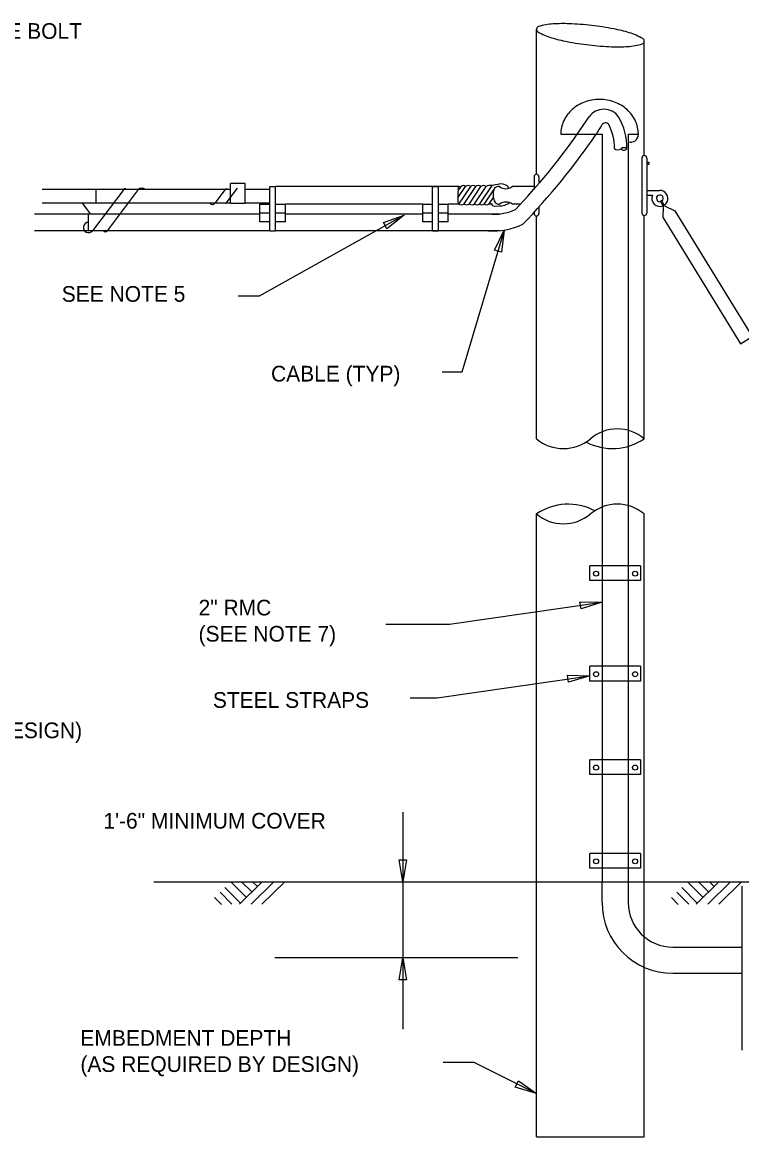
# Model space of a CAD drawing. Extents: x 1299104.8 to 1299141.6, y 239639.8 to 239661.8.
# Drawn here: x 1299124.15 to 1299129.65, y 239645.25 to 239653.76 of the extents above; entities that cross this region are included whole.
import ezdxf

# ---------------------------------------------------------------- set-up
doc = ezdxf.new("R2010")
doc.units = 0
doc.layers.add('DIM TXT', color=7, linetype='Continuous')

msp = doc.modelspace()

# ---------------------------------------------------------------- linework, layer by layer
at = {"layer": 'DIM TXT'}
for p, q in [((1299128.0798, 239652.6017), (1299128.0798, 239653.7122)), ((1299128.9048, 239652.7446), (1299128.9048, 239653.6171)), ((1299128.3917, 239652.9076), (1299128.4821, 239653.0418)), ((1299128.2653, 239652.9076), (1299128.5815, 239652.9076)), ((1299128.5815, 239652.9076), (1299128.5815, 239650.6817)), ((1299128.7815, 239652.9076), (1299128.7815, 239650.6929)), ((1299128.7815, 239652.9076), (1299128.8594, 239652.9076)), ((1299128.886, 239652.7258), (1299128.886, 239652.3058)), ((1299128.9235, 239652.7258), (1299128.9235, 239652.3058)), ((1299128.9235, 239652.6952), (1299128.9385, 239652.6952)), ((1299128.9235, 239652.6802), (1299128.9385, 239652.6802)), ((1299128.9385, 239652.6952), (1299128.9385, 239652.6802)), ((1299128.061, 239652.583), (1299128.061, 239652.4875)), ((1299128.0985, 239652.583), (1299128.0985, 239652.5305)), ((1299125.7398, 239652.4857), (1299124.2985, 239652.4857)), ((1299124.9225, 239652.4857), (1299124.6837, 239652.1707)), ((1299124.711, 239652.3807), (1299124.711, 239652.4857)), ((1299125.034, 239652.4857), (1299124.7953, 239652.1707)), ((1299125.6983, 239652.4857), (1299125.6187, 239652.3807)), ((1299125.7915, 239652.4963), (1299125.7039, 239652.3807)), ((1299125.7398, 239652.3807), (1299125.7398, 239652.5307)), ((1299125.8523, 239652.5307), (1299125.7398, 239652.5307)), ((1299125.8523, 239652.3807), (1299125.8523, 239652.5307)), ((1299126.0398, 239652.4857), (1299125.8523, 239652.4857)), ((1299126.0398, 239652.1707), (1299126.0398, 239652.5082)), ((1299126.0398, 239652.5082), (1299126.0848, 239652.5082)), ((1299126.0848, 239652.1707), (1299126.0848, 239652.5082)), ((1299127.485, 239652.5082), (1299126.0848, 239652.5082)), ((1299127.2848, 239652.1707), (1299127.2848, 239652.5082)), ((1299127.2848, 239652.5082), (1299127.3298, 239652.5082)), ((1299127.3298, 239652.1707), (1299127.3298, 239652.5082)), ((1299127.4789, 239652.4213), (1299127.5369, 239652.5082)), ((1299127.4821, 239652.5082), (1299127.4792, 239652.4291)), ((1299127.4809, 239652.4745), (1299127.5043, 239652.5096)), ((1299127.4821, 239652.5082), (1299127.505, 239652.5106)), ((1299127.4868, 239652.3732), (1299127.5769, 239652.5082)), ((1299127.5268, 239652.3755), (1299127.6153, 239652.5082)), ((1299127.5666, 239652.3755), (1299127.6551, 239652.5082)), ((1299127.6065, 239652.3755), (1299127.695, 239652.5082)), ((1299127.6464, 239652.3755), (1299127.7404, 239652.5164)), ((1299127.6818, 239652.3755), (1299127.7529, 239652.4821)), ((1299127.7536, 239652.5176), (1299127.7369, 239652.5161)), ((1299127.7663, 239652.5212), (1299127.7536, 239652.5176)), ((1299127.785, 239652.5237), (1299127.7663, 239652.5212)), ((1299127.8048, 239652.5283), (1299127.785, 239652.5237)), ((1299127.824, 239652.5252), (1299127.8048, 239652.5283)), ((1299127.8402, 239652.5212), (1299127.824, 239652.5252)), ((1299127.861, 239652.5121), (1299127.8402, 239652.5212)), ((1299127.8691, 239652.4943), (1299127.861, 239652.5121)), ((1299128.061, 239652.5082), (1299127.8949, 239652.5082)), ((1299128.9235, 239652.4787), (1299129.0236, 239652.4787)), ((1299125.7398, 239652.3807), (1299124.2985, 239652.3807)), ((1299124.6702, 239652.2982), (1299124.6077, 239652.3807)), ((1299125.7398, 239652.3807), (1299125.8523, 239652.3807)), ((1299126.0398, 239652.3807), (1299125.8523, 239652.3807)), ((1299127.4792, 239652.4291), (1299127.4778, 239652.3981)), ((1299127.4778, 239652.3981), (1299127.4792, 239652.3892)), ((1299127.4792, 239652.3892), (1299127.4868, 239652.3732)), ((1299127.7173, 239652.3755), (1299127.75, 239652.4245)), ((1299127.864, 239652.3758), (1299127.8463, 239652.3678)), ((1299127.8706, 239652.3865), (1299127.864, 239652.3758)), ((1299128.9235, 239652.4412), (1299128.9672, 239652.4412)), ((1299129.0377, 239652.4011), (1299129.0293, 239652.3966)), ((1299129.0517, 239652.3548), (1299129.0293, 239652.3966)), ((1299129.059, 239652.3614), (1299129.0377, 239652.4011)), ((1299125.9648, 239652.2982), (1299124.2398, 239652.2982)), ((1299124.6523, 239652.1707), (1299124.6523, 239652.2982)), ((1299125.9648, 239652.2382), (1299125.9648, 239652.3732)), ((1299125.9648, 239652.3732), (1299126.0398, 239652.3732)), ((1299126.0398, 239652.3057), (1299125.9648, 239652.3057)), ((1299126.0848, 239652.3732), (1299126.1598, 239652.3732)), ((1299126.1598, 239652.3057), (1299126.0848, 239652.3057)), ((1299126.1598, 239652.2382), (1299126.1598, 239652.3732)), ((1299127.2098, 239652.3732), (1299126.1598, 239652.3732)), ((1299127.2098, 239652.2982), (1299126.1598, 239652.2982)), ((1299127.2098, 239652.2382), (1299127.2098, 239652.3732)), ((1299127.2098, 239652.3732), (1299127.2848, 239652.3732)), ((1299127.2848, 239652.3057), (1299127.2098, 239652.3057)), ((1299127.3298, 239652.3732), (1299127.4048, 239652.3732)), ((1299127.4048, 239652.3057), (1299127.3298, 239652.3057)), ((1299127.4048, 239652.2382), (1299127.4048, 239652.3732)), ((1299127.4868, 239652.3732), (1299127.4048, 239652.3732)), ((1299127.8004, 239652.2982), (1299127.4048, 239652.2982)), ((1299127.7283, 239652.3739), (1299127.7187, 239652.3728)), ((1299127.7339, 239652.3739), (1299127.7283, 239652.3739)), ((1299127.743, 239652.3743), (1299127.7339, 239652.3739)), ((1299127.7386, 239652.3673), (1299127.7339, 239652.3739)), ((1299127.7462, 239652.3618), (1299127.7386, 239652.3673)), ((1299127.7582, 239652.3553), (1299127.7462, 239652.3618)), ((1299127.7967, 239652.3586), (1299127.7582, 239652.3553)), ((1299127.8139, 239652.3582), (1299127.7967, 239652.3586)), ((1299127.8245, 239652.3612), (1299127.8139, 239652.3582)), ((1299127.8356, 239652.3627), (1299127.8245, 239652.3612)), ((1299127.8463, 239652.3678), (1299127.8356, 239652.3627)), ((1299127.9566, 239652.3732), (1299127.8964, 239652.3732)), ((1299128.061, 239652.3112), (1299128.061, 239652.3024)), ((1299128.0985, 239652.3522), (1299128.0985, 239652.3024)), ((1299129.0495, 239652.2684), (1299129.0517, 239652.3548)), ((1299129.059, 239652.3614), (1299129.139, 239652.3235)), ((1299129.139, 239652.3235), (1299129.731, 239651.3613)), ((1299127.069, 239652.2891), (1299125.9581, 239651.6699)), ((1299126.0398, 239652.2382), (1299125.9648, 239652.2382)), ((1299126.1598, 239652.2382), (1299126.0848, 239652.2382)), ((1299127.2848, 239652.2382), (1299127.2098, 239652.2382)), ((1299127.4048, 239652.2382), (1299127.3298, 239652.2382)), ((1299128.0798, 239650.5805), (1299128.0798, 239652.2836)), ((1299128.5815, 239652.2506), (1299128.5815, 239647.1944)), ((1299128.7815, 239652.2618), (1299128.7815, 239647.1944)), ((1299128.9048, 239650.5805), (1299128.9048, 239652.2871)), ((1299129.0495, 239652.2684), (1299129.6416, 239651.3063)), ((1299126.0398, 239652.1707), (1299124.2398, 239652.1707)), ((1299126.0398, 239652.1707), (1299126.0848, 239652.1707)), ((1299127.8004, 239652.1707), (1299126.0848, 239652.1707)), ((1299127.2848, 239652.1707), (1299127.3298, 239652.1707)), ((1299127.8333, 239652.1748), (1299127.5087, 239651.0887)), ((1299125.9581, 239651.6699), (1299125.7968, 239651.6699)), ((1299129.6416, 239651.3063), (1299129.731, 239651.3613)), ((1299127.5087, 239651.0887), (1299127.3587, 239651.0887)), ((1299128.0798, 239647.1944), (1299128.0798, 239650.0052)), ((1299128.9048, 239647.1944), (1299128.9048, 239650.0052)), ((1299128.8755, 239649.6094), (1299128.4875, 239649.6094)), ((1299128.4875, 239649.4969), (1299128.4875, 239649.6094)), ((1299128.8755, 239649.6094), (1299128.8755, 239649.4969)), ((1299128.8755, 239649.4969), (1299128.4875, 239649.4969)), ((1299127.4155, 239649.1637), (1299128.5815, 239649.3313)), ((1299126.9279, 239649.1637), (1299127.4155, 239649.1637)), ((1299128.8755, 239648.8409), (1299128.4875, 239648.8409)), ((1299128.4875, 239648.7284), (1299128.4875, 239648.8409)), ((1299128.8755, 239648.8409), (1299128.8755, 239648.7284)), ((1299127.3215, 239648.5999), (1299128.4875, 239648.7675)), ((1299128.8755, 239648.7284), (1299128.4875, 239648.7284)), ((1299127.1126, 239648.5999), (1299127.3215, 239648.5999)), ((1299128.4875, 239648.0143), (1299128.4875, 239648.1268)), ((1299128.8755, 239648.1268), (1299128.4875, 239648.1268)), ((1299128.8755, 239648.1268), (1299128.8755, 239648.0143)), ((1299128.8755, 239648.0143), (1299128.4875, 239648.0143)), ((1299127.0573, 239647.7268), (1299127.0573, 239646.0673)), ((1299128.8755, 239647.4105), (1299128.4875, 239647.4105)), ((1299128.4875, 239647.298), (1299128.4875, 239647.4105)), ((1299128.8755, 239647.4105), (1299128.8755, 239647.298)), ((1299128.8755, 239647.298), (1299128.4875, 239647.298)), ((1299125.1536, 239647.1944), (1299131.9317, 239647.1944)), ((1299125.7411, 239647.1944), (1299125.8608, 239647.0737)), ((1299125.8086, 239647.0228), (1299125.9815, 239647.1944)), ((1299125.8242, 239647.1944), (1299125.9018, 239647.1162)), ((1299125.8968, 239647.0225), (1299126.07, 239647.1944)), ((1299125.9084, 239647.1944), (1299125.9447, 239647.1579)), ((1299125.9803, 239647.0222), (1299126.1538, 239647.1944)), ((1299128.0798, 239645.2453), (1299128.0798, 239647.1944)), ((1299128.5815, 239647.036), (1299128.5815, 239647.1964)), ((1299128.7815, 239647.1944), (1299128.7815, 239647.036)), ((1299128.9048, 239645.2453), (1299128.9048, 239647.1944)), ((1299129.235, 239647.1944), (1299129.3548, 239647.0737)), ((1299129.3026, 239647.0228), (1299129.4754, 239647.1944)), ((1299129.3182, 239647.1944), (1299129.3957, 239647.1162)), ((1299129.3908, 239647.0225), (1299129.564, 239647.1944)), ((1299129.4024, 239647.1944), (1299129.4386, 239647.1579)), ((1299129.4743, 239647.0222), (1299129.6478, 239647.1944)), ((1299125.6595, 239647.1144), (1299125.7501, 239647.023)), ((1299125.6968, 239647.1514), (1299125.8161, 239647.0312)), ((1299129.1535, 239647.1144), (1299129.2441, 239647.023)), ((1299129.1908, 239647.1514), (1299129.3101, 239647.0312)), ((1299129.6499, 239647.1607), (1299129.65, 239646.2247)), ((1299125.6177, 239647.0727), (1299125.6694, 239647.0206)), ((1299129.1116, 239647.0727), (1299129.1633, 239647.0206)), ((1299129.123, 239646.6944), (1299129.6499, 239646.6944)), ((1299127.9363, 239646.6122), (1299126.0781, 239646.6122)), ((1299129.123, 239646.4944), (1299129.6499, 239646.4944)), ((1299129.65, 239646.247), (1299129.65, 239645.9071)), ((1299129.6495, 239646.2246), (1299129.6483, 239646.2245)), ((1299127.366, 239645.8146), (1299127.5998, 239645.8146)), ((1299127.5998, 239645.8146), (1299128.0798, 239645.5751)), ((1299128.0798, 239645.2453), (1299128.9048, 239645.2453))]:
    msp.add_line(p, q, dxfattribs=at)
for points in [[(1299126.9351, 239652.1859), (1299126.9093, 239652.2338), (1299127.069, 239652.2891)], [(1299127.8116, 239652.0072), (1299127.7595, 239652.0227), (1299127.8333, 239652.1748)], [(1299128.4205, 239649.2797), (1299128.4124, 239649.3335), (1299128.5815, 239649.3313)], [(1299128.3256, 239648.7186), (1299128.3185, 239648.7725), (1299128.4875, 239648.7675)], [(1299127.0301, 239647.3612), (1299127.0845, 239647.3612), (1299127.0573, 239647.1944)], [(1299127.0845, 239646.4454), (1299127.0301, 239646.4454), (1299127.0573, 239646.6122)], [(1299127.9179, 239645.6238), (1299127.9417, 239645.6727), (1299128.0798, 239645.5751)]]:
    msp.add_lwpolyline(points, close=True, dxfattribs=at)
for centre in [(1299128.5357, 239649.5491), (1299128.8339, 239649.5491), (1299128.5357, 239648.7806), (1299128.8339, 239648.7806), (1299128.5357, 239648.0665), (1299128.8339, 239648.0665), (1299128.5357, 239647.3502), (1299128.8339, 239647.3502)]:
    msp.add_circle(centre, 0.0192, dxfattribs=at)
for centre, radius, start, end in [((1299128.2379, 239653.2633), 0.4887, 93.66612, 106.98781), ((1299128.2824, 239652.5686), 1.1847, 87.70627, 93.66612), ((1299128.2379, 239651.4567), 2.2976, 83.42757, 87.70627), ((1299128.2379, 239651.4567), 2.2976, 79.14886, 83.42757), ((1299128.1015, 239653.7097), 0.0219, 173.42757, 239.86732), ((1299128.1015, 239653.7097), 0.0219, 106.98781, 173.42757), ((1299128.3359, 239654.1134), 0.4887, 239.86732, 253.18901), ((1299128.4474, 239652.5496), 1.1847, 73.18901, 79.14886), ((1299128.6487, 239653.2159), 0.4887, 59.86732, 73.18901), ((1299128.5372, 239654.7797), 1.1847, 253.18901, 259.14886), ((1299128.7467, 239655.8726), 2.2976, 259.14886, 263.42757), ((1299128.7467, 239655.8726), 2.2976, 263.42757, 267.70627), ((1299128.7021, 239654.7607), 1.1847, 267.70627, 273.66612), ((1299128.7466, 239654.066), 0.4887, 273.66612, 286.98781), ((1299128.883, 239653.6196), 0.0219, 286.98781, 353.42757), ((1299128.883, 239653.6196), 0.0219, 353.42757, 59.86732), ((1299128.5508, 239652.8749), 0.2971, 110.38498, 131.89584), ((1299128.5624, 239652.8436), 0.3305, 90, 110.38498), ((1299128.5624, 239652.8436), 0.3305, 69.61502, 90), ((1299128.574, 239652.8749), 0.2971, 48.10416, 69.61502), ((1299128.5329, 239652.8948), 0.2703, 131.89584, 155.21648), ((1299128.5953, 239652.958), 0.1408, 36.49507, 143.50493), ((1299128.5919, 239652.8948), 0.2703, 24.78352, 48.10416), ((1299128.5051, 239652.9076), 0.2398, 155.21648, 180), ((1299129.0735, 239652.6328), 0.6022, 144.87667, 152.85048), ((1299128.6078, 239652.9646), 0.0306, 34.34465, 151.37722), ((1299128.2914, 239652.8049), 0.3848, 359.06907, 27.39103), ((1299128.2914, 239652.8049), 0.4797, 359.06907, 29.59041), ((1299128.6196, 239652.9076), 0.2398, 360, 24.78352), ((1299124.5372, 239655.6019), 4.7029, 315.97069, 325.04698), ((1299124.1117, 239655.9554), 5.3738, 315.95645, 325.44782), ((1299128.8002, 239652.9062), 0.0592, 251.52788, 1.3406), ((1299128.7489, 239652.7695), 0.0354, 51.23396, 128.76604), ((1299128.7023, 239652.8275), 0.039, 227.746, 308.76604), ((1299128.7474, 239652.8148), 0.0296, 220.37691, 323.1828), ((1299128.9048, 239652.7258), 0.0187, 0, 180), ((1299128.0798, 239652.583), 0.0187, 0, 180), ((1299124.9315, 239652.4798), 0.0109, 33.21794, 146.78206), ((1299125.0604, 239652.4526), 0.0423, 51.49023, 128.50977), ((1299125.7079, 239652.4784), 0.0121, 37.01713, 142.98287), ((1299127.5198, 239652.4894), 0.0254, 47.66391, 133.46069), ((1299127.5569, 239652.4826), 0.0325, 51.98323, 128.01677), ((1299127.5953, 239652.4826), 0.0325, 51.98323, 128.01677), ((1299127.6351, 239652.4826), 0.0325, 51.98323, 128.01677), ((1299127.675, 239652.4826), 0.0325, 51.98323, 128.01677), ((1299127.7287, 239652.4445), 0.0721, 83.48218, 117.87794), ((1299127.8844, 239652.4465), 0.1362, 159.55921, 206.64556), ((1299127.7963, 239652.4456), 0.0626, 89.15947, 129.18185), ((1299127.8461, 239652.5722), 0.0805, 232.63143, 307.36857), ((1299129.0236, 239652.4176), 0.0612, 334.64706, 90), ((1299125.6003, 239652.3934), 0.0223, 214.62132, 325.37868), ((1299125.7029, 239652.3811), 0.00109, 198.27859, 341.72141), ((1299127.5045, 239652.4128), 0.0434, 245.83442, 300.81788), ((1299127.5444, 239652.4128), 0.0434, 245.83442, 300.81788), ((1299127.5843, 239652.4128), 0.0434, 245.83442, 300.81788), ((1299127.6242, 239652.4128), 0.0434, 245.83442, 300.81788), ((1299127.6596, 239652.4128), 0.0434, 245.83442, 300.81788), ((1299127.6951, 239652.4128), 0.0434, 245.83442, 300.81788), ((1299127.8039, 239652.4472), 0.0743, 236.21474, 264.83354), ((1299127.8468, 239652.3072), 0.0825, 53.07212, 126.92788), ((1299129.0236, 239652.4176), 0.0612, 157.22558, 293.64255), ((1299129.0236, 239652.4176), 0.0259, 308.46642, 287.3643), ((1299129.0236, 239652.4176), 0.0612, 302.55083, 334.64706), ((1299127.7563, 239652.6628), 0.3672, 263.10157, 296.20348), ((1299128.0798, 239652.3024), 0.0187, 180, 200.84059), ((1299128.0798, 239652.3024), 0.0187, 180, 0), ((1299128.0798, 239652.3024), 0.0187, 341.22029, 0), ((1299128.9048, 239652.3058), 0.0187, 180, 0), ((1299124.6527, 239652.195), 0.0394, 90.50415, 321.92714), ((1299127.7563, 239652.6628), 0.494, 264.87793, 296.20348), ((1299124.7811, 239652.1798), 0.0168, 212.51792, 327.48208), ((1299128.6985, 239650.3344), 0.3211, 50.03379, 129.96621), ((1299128.286, 239650.8266), 0.3211, 230.03379, 309.96621), ((1299128.661, 239650.9391), 0.4336, 242.14831, 304.20546), ((1299128.3235, 239649.6466), 0.4336, 62.14831, 124.20546), ((1299128.6985, 239649.7591), 0.3211, 50.03379, 129.96621), ((1299128.286, 239650.2513), 0.3211, 230.03379, 309.96621), ((1299129.123, 239647.036), 0.5416, 180, 270), ((1299129.123, 239647.036), 0.3416, 180, 270)]:
    msp.add_arc(centre, radius, start, end, dxfattribs=at)

# ---------------------------------------------------------------- texts
for s, p in [('3/4" THIMBLE EYE BOLT', (1299122.7536, 239653.6372)), ('SEE NOTE 5', (1299124.4487, 239651.6273)), ('CABLE (TYP) ', (1299126.0493, 239651.0177)), ('2" RMC', (1299125.4951, 239649.2296)), ('(SEE NOTE 7)', (1299125.4951, 239649.0296)), ('STEEL STRAPS', (1299125.6047, 239648.5233)), ('(AS REQUIRED BY DESIGN)', (1299122.4733, 239648.2916)), ('1\'-6" MINIMUM COVER', (1299124.7669, 239647.6002)), ('EMBEDMENT DEPTH', (1299124.5912, 239645.9402)), ('(AS REQUIRED BY DESIGN)', (1299124.5912, 239645.7402))]:
    msp.add_text(s, height=0.12, dxfattribs=at).set_placement(p)

doc.saveas('drawing.dxf')
